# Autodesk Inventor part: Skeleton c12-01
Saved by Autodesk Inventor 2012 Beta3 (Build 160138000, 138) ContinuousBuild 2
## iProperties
Created: 2011-01
Part Number: Skeleton c12-01
Material: Default
Document SubType Name: Modeling
Designer: Beta-8540w
Density: 1 g/cm^3
_SkeletonDoc: Frame Skeleton File
_Version: 15.0.0
Author: Beta-8540w
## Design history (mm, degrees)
sketch "Reference Skeleton"
  geometry: L1 through (75, 55) direction (1, 0); L2 through (15, 160) direction (1, -0); L3 through (15, 190) direction (1, 0); L4 through (75, 295) direction (1, 0); 33 other entities
  constraints: 20 horizontal
